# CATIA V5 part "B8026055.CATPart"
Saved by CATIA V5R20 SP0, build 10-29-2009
Part number: B8026055
Revision: 3
Definition: design
Nomenclature: B8026055
Source: made
Description: NOT SPECIFIED
Bounding box of the stored display mesh (mm): x -45.5 to 45.5, y -45.306 to 45.306, z -25 to 55
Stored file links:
  C:\Users\Utente\Desktop\3D files B802\B8026055.CATPart
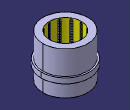
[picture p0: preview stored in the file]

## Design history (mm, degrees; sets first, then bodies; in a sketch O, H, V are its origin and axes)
Body1 "MANIFOLD_SOLID_BREP #38" (main body)
  Solid1: solid without history
Body2 "MANIFOLD_SOLID_BREP #76"
  Solid2: solid without history
Body3 "MANIFOLD_SOLID_BREP #114"
  Solid3: solid without history
Body4 "MANIFOLD_SOLID_BREP #152"
  Solid4: solid without history
Body5 "MANIFOLD_SOLID_BREP #190"
  Solid5: solid without history
Body6 "MANIFOLD_SOLID_BREP #228"
  Solid6: solid without history
Body7 "MANIFOLD_SOLID_BREP #266"
  Solid7: solid without history
Body8 "MANIFOLD_SOLID_BREP #304"
  Solid8: solid without history
Body9 "MANIFOLD_SOLID_BREP #2840"
  Solid9: solid without history
Body10 "MANIFOLD_SOLID_BREP #2878"
  Solid10: solid without history
Body11 "MANIFOLD_SOLID_BREP #2916"
  Solid11: solid without history
Body12 "MANIFOLD_SOLID_BREP #2954"
  Solid12: solid without history
Body13 "MANIFOLD_SOLID_BREP #2992"
  Solid13: solid without history
Body14 "MANIFOLD_SOLID_BREP #3030"
  Solid14: solid without history
Body15 "MANIFOLD_SOLID_BREP #3068"
  Solid15: solid without history
Body16 "MANIFOLD_SOLID_BREP #3106"
  Solid16: solid without history
Body17 "MANIFOLD_SOLID_BREP #3144"
  Solid17: solid without history
Body18 "MANIFOLD_SOLID_BREP #3182"
  Solid18: solid without history
Body19 "MANIFOLD_SOLID_BREP #3220"
  Solid19: solid without history
Body20 "MANIFOLD_SOLID_BREP #3258"
  Solid20: solid without history
Body21 "MANIFOLD_SOLID_BREP #3296"
  Solid21: solid without history
Body22 "MANIFOLD_SOLID_BREP #3334"
  Solid22: solid without history
Body23 "MANIFOLD_SOLID_BREP #3372"
  Solid23: solid without history
Body24 "MANIFOLD_SOLID_BREP #3410"
  Solid24: solid without history
Body25 "MANIFOLD_SOLID_BREP #3448"
  Solid25: solid without history
Body26 "MANIFOLD_SOLID_BREP #3486"
  Solid26: solid without history
Body27 "MANIFOLD_SOLID_BREP #3524"
  Solid27: solid without history
Body28 "MANIFOLD_SOLID_BREP #3562"
  Solid28: solid without history
Body29 "MANIFOLD_SOLID_BREP #3600"
  Solid29: solid without history
Body30 "MANIFOLD_SOLID_BREP #3638"
  Solid30: solid without history
Body31 "MANIFOLD_SOLID_BREP #3676"
  Solid31: solid without history
Body32 "MANIFOLD_SOLID_BREP #3714"
  Solid32: solid without history
Body33 "MANIFOLD_SOLID_BREP #3752"
  Solid33: solid without history
Body34 "MANIFOLD_SOLID_BREP #3790"
  Solid34: solid without history
Body35 "MANIFOLD_SOLID_BREP #3828"
  Solid35: solid without history
Body36 "MANIFOLD_SOLID_BREP #3866"
  Solid36: solid without history
Body37 "MANIFOLD_SOLID_BREP #3904"
  Solid37: solid without history
Body38 "MANIFOLD_SOLID_BREP #3942"
  Solid38: solid without history
Body39 "MANIFOLD_SOLID_BREP #3980"
  Solid39: solid without history
Body40 "MANIFOLD_SOLID_BREP #4018"
  Solid40: solid without history
Body41 "MANIFOLD_SOLID_BREP #4056"
  Solid41: solid without history
Body42 "MANIFOLD_SOLID_BREP #4094"
  Solid42: solid without history
Body43 "MANIFOLD_SOLID_BREP #4132"
  Solid43: solid without history
Body44 "MANIFOLD_SOLID_BREP #4170"
  Solid44: solid without history
Body45 "MANIFOLD_SOLID_BREP #4208"
  Solid45: solid without history
Body46 "MANIFOLD_SOLID_BREP #4246"
  Solid46: solid without history
Body47 "MANIFOLD_SOLID_BREP #4284"
  Solid47: solid without history
Body48 "MANIFOLD_SOLID_BREP #4322"
  Solid48: solid without history
Body49 "MANIFOLD_SOLID_BREP #4360"
  Solid49: solid without history
Body50 "MANIFOLD_SOLID_BREP #4398"
  Solid50: solid without history
Body51 "MANIFOLD_SOLID_BREP #4436"
  Solid51: solid without history
Body52 "MANIFOLD_SOLID_BREP #4474"
  Solid52: solid without history
Body53 "MANIFOLD_SOLID_BREP #4512"
  Solid53: solid without history
Body54 "MANIFOLD_SOLID_BREP #4550"
  Solid54: solid without history
Body55 "MANIFOLD_SOLID_BREP #4588"
  Solid55: solid without history
Body56 "MANIFOLD_SOLID_BREP #4626"
  Solid56: solid without history
Body57 "MANIFOLD_SOLID_BREP #4664"
  Solid57: solid without history
Body58 "MANIFOLD_SOLID_BREP #4702"
  Solid58: solid without history
Body59 "MANIFOLD_SOLID_BREP #4740"
  Solid59: solid without history
Body60 "MANIFOLD_SOLID_BREP #4778"
  Solid60: solid without history
Body61 "MANIFOLD_SOLID_BREP #4816"
  Solid61: solid without history
Body62 "MANIFOLD_SOLID_BREP #4854"
  Solid62: solid without history
Body63 "MANIFOLD_SOLID_BREP #4892"
  Solid63: solid without history
Body64 "MANIFOLD_SOLID_BREP #4930"
  Solid64: solid without history
Body65 "MANIFOLD_SOLID_BREP #4968"
  Solid65: solid without history
Body66 "MANIFOLD_SOLID_BREP #5006"
  Solid66: solid without history
Body67 "MANIFOLD_SOLID_BREP #5044"
  Solid67: solid without history
Body68 "MANIFOLD_SOLID_BREP #5082"
  Solid68: solid without history
Body69 "MANIFOLD_SOLID_BREP #5120"
  Solid69: solid without history
Body70 "MANIFOLD_SOLID_BREP #5158"
  Solid70: solid without history
Body71 "MANIFOLD_SOLID_BREP #5196"
  Solid71: solid without history
Body72 "MANIFOLD_SOLID_BREP #5234"
  Solid72: solid without history
Body73 "MANIFOLD_SOLID_BREP #5272"
  Solid73: solid without history
Body74 "MANIFOLD_SOLID_BREP #5310"
  Solid74: solid without history
Body75 "MANIFOLD_SOLID_BREP #5348"
  Solid75: solid without history
Body76 "MANIFOLD_SOLID_BREP #5386"
  Solid76: solid without history
Body77 "MANIFOLD_SOLID_BREP #5424"
  Solid77: solid without history
Body78 "MANIFOLD_SOLID_BREP #5462"
  Solid78: solid without history
Body79 "MANIFOLD_SOLID_BREP #5500"
  Solid79: solid without history
Body80 "MANIFOLD_SOLID_BREP #5538"
  Solid80: solid without history
Body81 "MANIFOLD_SOLID_BREP #5576"
  Solid81: solid without history
Body82 "MANIFOLD_SOLID_BREP #5614"
  Solid82: solid without history
Body83 "MANIFOLD_SOLID_BREP #5652"
  Solid83: solid without history
Body84 "MANIFOLD_SOLID_BREP #5690"
  Solid84: solid without history
Body85 "MANIFOLD_SOLID_BREP #5728"
  Solid85: solid without history
Body86 "MANIFOLD_SOLID_BREP #5766"
  Solid86: solid without history
Body87 "MANIFOLD_SOLID_BREP #5804"
  Solid87: solid without history
Body88 "MANIFOLD_SOLID_BREP #5842"
  Solid88: solid without history
Body89 "MANIFOLD_SOLID_BREP #5880"
  Solid89: solid without history
Body90 "MANIFOLD_SOLID_BREP #5918"
  Solid90: solid without history
Body91 "MANIFOLD_SOLID_BREP #5956"
  Solid91: solid without history
Body92 "MANIFOLD_SOLID_BREP #5994"
  Solid92: solid without history
Body93 "MANIFOLD_SOLID_BREP #6032"
  Solid93: solid without history
Body94 "MANIFOLD_SOLID_BREP #6070"
  Solid94: solid without history
Body95 "MANIFOLD_SOLID_BREP #6108"
  Solid95: solid without history
Body96 "MANIFOLD_SOLID_BREP #6146"
  Solid96: solid without history
Body97 "MANIFOLD_SOLID_BREP #6184"
  Solid97: solid without history
Body98 "MANIFOLD_SOLID_BREP #6222"
  Solid98: solid without history
Body99 "MANIFOLD_SOLID_BREP #6260"
  Solid99: solid without history
Body100 "MANIFOLD_SOLID_BREP #6298"
  Solid100: solid without history
Body101 "MANIFOLD_SOLID_BREP #6336"
  Solid101: solid without history
Body102 "MANIFOLD_SOLID_BREP #6374"
  Solid102: solid without history
Body103 "MANIFOLD_SOLID_BREP #6412"
  Solid103: solid without history
Body104 "MANIFOLD_SOLID_BREP #6450"
  Solid104: solid without history
Body105 "MANIFOLD_SOLID_BREP #6488"
  Solid105: solid without history
Body106 "MANIFOLD_SOLID_BREP #6526"
  Solid106: solid without history
Body107 "MANIFOLD_SOLID_BREP #6564"
  Solid107: solid without history
Body108 "MANIFOLD_SOLID_BREP #6602"
  Solid108: solid without history
Body109 "MANIFOLD_SOLID_BREP #6640"
  Solid109: solid without history
Body110 "MANIFOLD_SOLID_BREP #6678"
  Solid110: solid without history
Body111 "MANIFOLD_SOLID_BREP #6716"
  Solid111: solid without history
Body112 "MANIFOLD_SOLID_BREP #6754"
  Solid112: solid without history
Body113 "MANIFOLD_SOLID_BREP #6792"
  Solid113: solid without history
Body114 "MANIFOLD_SOLID_BREP #6830"
  Solid114: solid without history
Body115 "MANIFOLD_SOLID_BREP #6868"
  Solid115: solid without history
Body116 "MANIFOLD_SOLID_BREP #6906"
  Solid116: solid without history
Body117 "MANIFOLD_SOLID_BREP #6944"
  Solid117: solid without history
Body118 "MANIFOLD_SOLID_BREP #6982"
  Solid118: solid without history
Body119 "MANIFOLD_SOLID_BREP #7020"
  Solid119: solid without history
Body120 "MANIFOLD_SOLID_BREP #7058"
  Solid120: solid without history
Body121 "MANIFOLD_SOLID_BREP #7096"
  Solid121: solid without history
Body122 "MANIFOLD_SOLID_BREP #7134"
  Solid122: solid without history
Body123 "MANIFOLD_SOLID_BREP #7172"
  Solid123: solid without history
Body124 "MANIFOLD_SOLID_BREP #7210"
  Solid124: solid without history
Body125 "MANIFOLD_SOLID_BREP #7248"
  Solid125: solid without history
Body126 "MANIFOLD_SOLID_BREP #7286"
  Solid126: solid without history
Body127 "MANIFOLD_SOLID_BREP #7324"
  Solid127: solid without history
Body128 "MANIFOLD_SOLID_BREP #7362"
  Solid128: solid without history
Body129 "MANIFOLD_SOLID_BREP #7400"
  Solid129: solid without history
Body130 "MANIFOLD_SOLID_BREP #7438"
  Solid130: solid without history
Body131 "MANIFOLD_SOLID_BREP #7476"
  Solid131: solid without history
Body132 "MANIFOLD_SOLID_BREP #7514"
  Solid132: solid without history
Body133 "MANIFOLD_SOLID_BREP #7552"
  Solid133: solid without history
Body134 "MANIFOLD_SOLID_BREP #7590"
  Solid134: solid without history
Body135 "MANIFOLD_SOLID_BREP #7628"
  Solid135: solid without history
Body136 "MANIFOLD_SOLID_BREP #7666"
  Solid136: solid without history
Body137 "MANIFOLD_SOLID_BREP #7704"
  Solid137: solid without history
Body138 "MANIFOLD_SOLID_BREP #7742"
  Solid138: solid without history
Body139 "MANIFOLD_SOLID_BREP #7780"
  Solid139: solid without history
Body140 "MANIFOLD_SOLID_BREP #7818"
  Solid140: solid without history
Body141 "MANIFOLD_SOLID_BREP #7856"
  Solid141: solid without history
Body142 "MANIFOLD_SOLID_BREP #7894"
  Solid142: solid without history
Body143 "MANIFOLD_SOLID_BREP #7932"
  Solid143: solid without history
Body144 "MANIFOLD_SOLID_BREP #7970"
  Solid144: solid without history
Body145 "MANIFOLD_SOLID_BREP #8008"
  Solid145: solid without history
Body146 "MANIFOLD_SOLID_BREP #8046"
  Solid146: solid without history
Body147 "MANIFOLD_SOLID_BREP #8084"
  Solid147: solid without history
Body148 "MANIFOLD_SOLID_BREP #8122"
  Solid148: solid without history
Body149 "MANIFOLD_SOLID_BREP #8160"
  Solid149: solid without history
Body150 "MANIFOLD_SOLID_BREP #8198"
  Solid150: solid without history
Body151 "MANIFOLD_SOLID_BREP #8236"
  Solid151: solid without history
Body152 "MANIFOLD_SOLID_BREP #8274"
  Solid152: solid without history
Body153 "MANIFOLD_SOLID_BREP #8312"
  Solid153: solid without history
Body154 "MANIFOLD_SOLID_BREP #8350"
  Solid154: solid without history
Body155 "MANIFOLD_SOLID_BREP #8388"
  Solid155: solid without history
Body156 "MANIFOLD_SOLID_BREP #8426"
  Solid156: solid without history
Body157 "MANIFOLD_SOLID_BREP #8464"
  Solid157: solid without history
Body158 "MANIFOLD_SOLID_BREP #8502"
  Solid158: solid without history
Body159 "MANIFOLD_SOLID_BREP #8540"
  Solid159: solid without history
Body160 "MANIFOLD_SOLID_BREP #8578"
  Solid160: solid without history
Body161 "MANIFOLD_SOLID_BREP #8616"
  Solid161: solid without history
Body162 "MANIFOLD_SOLID_BREP #8654"
  Solid162: solid without history
Body163 "MANIFOLD_SOLID_BREP #8692"
  Solid163: solid without history
Body164 "MANIFOLD_SOLID_BREP #8730"
  Solid164: solid without history
Body165 "MANIFOLD_SOLID_BREP #8768"
  Solid165: solid without history
Body166 "MANIFOLD_SOLID_BREP #8806"
  Solid166: solid without history
Body167 "MANIFOLD_SOLID_BREP #8844"
  Solid167: solid without history
Body168 "MANIFOLD_SOLID_BREP #8882"
  Solid168: solid without history
Body169 "MANIFOLD_SOLID_BREP #8920"
  Solid169: solid without history
Body170 "MANIFOLD_SOLID_BREP #8958"
  Solid170: solid without history
Body171 "MANIFOLD_SOLID_BREP #8996"
  Solid171: solid without history
Body172 "MANIFOLD_SOLID_BREP #9034"
  Solid172: solid without history
Body173 "MANIFOLD_SOLID_BREP #9072"
  Solid173: solid without history
Body174 "MANIFOLD_SOLID_BREP #9110"
  Solid174: solid without history
Body175 "MANIFOLD_SOLID_BREP #9148"
  Solid175: solid without history
Body176 "MANIFOLD_SOLID_BREP #9186"
  Solid176: solid without history
Body177 "MANIFOLD_SOLID_BREP #9224"
  Solid177: solid without history
Body178 "MANIFOLD_SOLID_BREP #9262"
  Solid178: solid without history
Body179 "MANIFOLD_SOLID_BREP #9300"
  Solid179: solid without history
Body180 "MANIFOLD_SOLID_BREP #9338"
  Solid180: solid without history
Body181 "MANIFOLD_SOLID_BREP #9376"
  Solid181: solid without history
Body182 "MANIFOLD_SOLID_BREP #9414"
  Solid182: solid without history
Body183 "MANIFOLD_SOLID_BREP #9452"
  Solid183: solid without history
Body184 "MANIFOLD_SOLID_BREP #9490"
  Solid184: solid without history
Body185 "MANIFOLD_SOLID_BREP #9528"
  Solid185: solid without history
Body186 "MANIFOLD_SOLID_BREP #9566"
  Solid186: solid without history
Body187 "MANIFOLD_SOLID_BREP #9604"
  Solid187: solid without history
Body188 "MANIFOLD_SOLID_BREP #9642"
  Solid188: solid without history
Body189 "MANIFOLD_SOLID_BREP #9680"
  Solid189: solid without history
Body190 "MANIFOLD_SOLID_BREP #9718"
  Solid190: solid without history
Body191 "MANIFOLD_SOLID_BREP #9756"
  Solid191: solid without history
Body192 "MANIFOLD_SOLID_BREP #9794"
  Solid192: solid without history
Body193 "MANIFOLD_SOLID_BREP #9832"
  Solid193: solid without history
Body194 "MANIFOLD_SOLID_BREP #9870"
  Solid194: solid without history
Body195 "MANIFOLD_SOLID_BREP #9908"
  Solid195: solid without history
Body196 "MANIFOLD_SOLID_BREP #9946"
  Solid196: solid without history
Body197 "MANIFOLD_SOLID_BREP #9984"
  Solid197: solid without history
Body198 "MANIFOLD_SOLID_BREP #10022"
  Solid198: solid without history
Body199 "MANIFOLD_SOLID_BREP #10060"
  Solid199: solid without history
Body200 "MANIFOLD_SOLID_BREP #10098"
  Solid200: solid without history
Body201 "MANIFOLD_SOLID_BREP #10136"
  Solid201: solid without history
Body202 "MANIFOLD_SOLID_BREP #10174"
  Solid202: solid without history
Body203 "MANIFOLD_SOLID_BREP #10212"
  Solid203: solid without history
Body204 "MANIFOLD_SOLID_BREP #10250"
  Solid204: solid without history
Body205 "MANIFOLD_SOLID_BREP #10288"
  Solid205: solid without history
Body206 "MANIFOLD_SOLID_BREP #10326"
  Solid206: solid without history
Body207 "MANIFOLD_SOLID_BREP #10364"
  Solid207: solid without history
Body208 "MANIFOLD_SOLID_BREP #10402"
  Solid208: solid without history
Body209 "MANIFOLD_SOLID_BREP #10440"
  Solid209: solid without history
Body210 "MANIFOLD_SOLID_BREP #10478"
  Solid210: solid without history
Body211 "MANIFOLD_SOLID_BREP #10516"
  Solid211: solid without history
Body212 "MANIFOLD_SOLID_BREP #10554"
  Solid212: solid without history
Body213 "MANIFOLD_SOLID_BREP #10592"
  Solid213: solid without history
Body214 "MANIFOLD_SOLID_BREP #10630"
  Solid214: solid without history
Body215 "MANIFOLD_SOLID_BREP #10668"
  Solid215: solid without history
Body216 "MANIFOLD_SOLID_BREP #10706"
  Solid216: solid without history
Body217 "MANIFOLD_SOLID_BREP #10744"
  Solid217: solid without history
